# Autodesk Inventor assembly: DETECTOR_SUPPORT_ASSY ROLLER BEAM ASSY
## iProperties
Shininess: 64.0
Length Units: 11272
Angle Units: 11279
Time Units: 11290
Mass Units: 11286
Length Display Precision: 3
Angle Display Precision: 2
Compacted: True
Part Number: DETECTOR_SUPPORT_ASSY ROLLER BEAM ASSY
Document SubType Name: Assembly
Created: 2004-08
Designer: John Blackburn
Manufacturer: Standard
Standards Organization: Custom
Density: 0.0
Volumn: 0.0
Area: 0.0
PropertySet Name: Model Information
Control State: 0
Master: False
Checked Out: False
Author: John Blackburn
